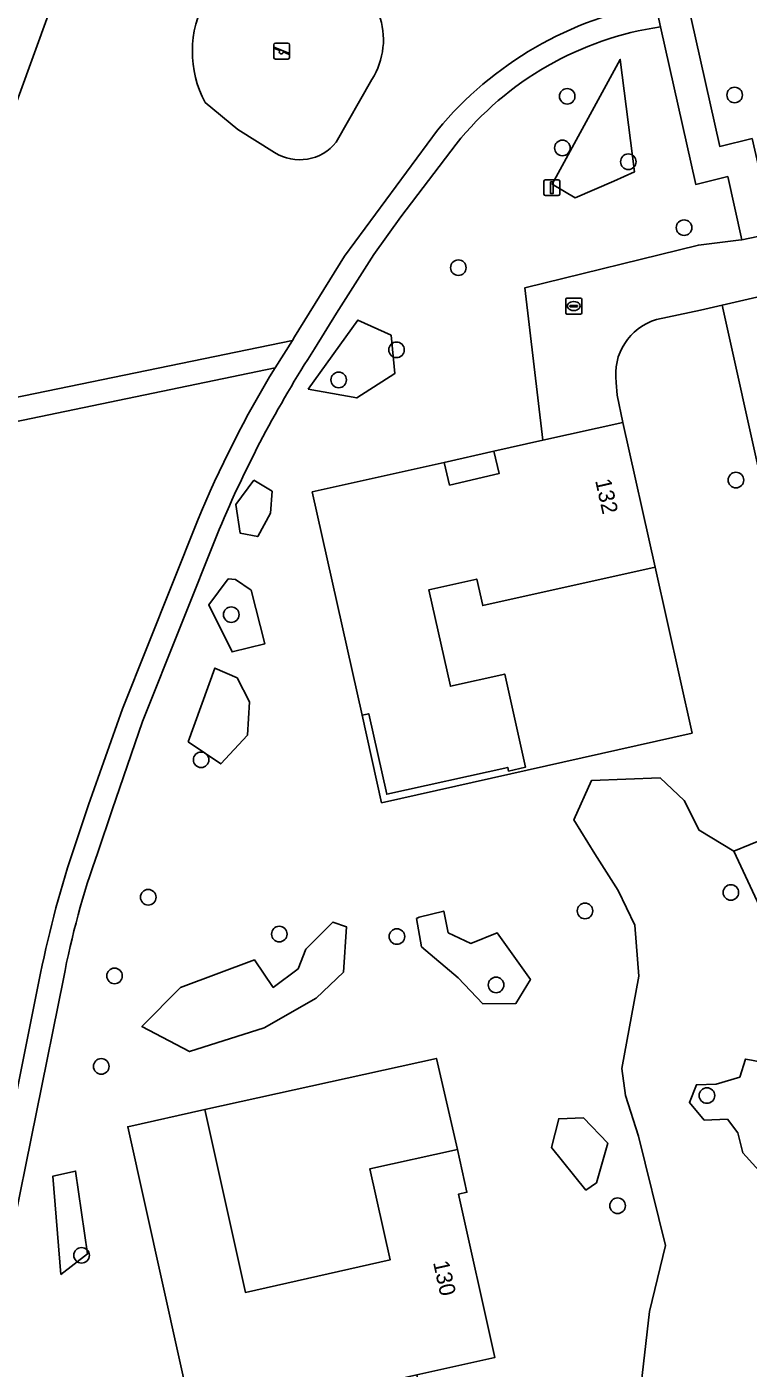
# Model space of a CAD drawing. Extents: x 156661 to 157576, y 383570 to 384425.
# Drawn here: x 156734.9 to 156780.2, y 383941.5 to 384025.8 of the extents above; entities that cross this region are included whole.
import ezdxf

# ---------------------------------------------------------------- set-up
doc = ezdxf.new("R2010")
doc.units = 0
for name, color, linetype in [('IMGEO_Boom', 7, 'Continuous'), ('IMGEO_Erf', 7, 'Continuous'), ('IMGEO_Groenvoorziening', 7, 'Continuous'), ('IMGEO_Lichtmast', 7, 'Continuous'), ('IMGEO_Meer_plas_ven_vijver', 7, 'Continuous'), ('IMGEO_Pand', 7, 'Continuous'), ('IMGEO_Pand_nummerreeks', 7, 'Continuous'), ('IMGEO_Pand_overbouw', 7, 'Continuous'), ('IMGEO_Rijbaan_lokaal_gesloten', 7, 'Continuous'), ('IMGEO_Rioolput', 7, 'Continuous'), ('IMGEO_Speelvoorziening', 7, 'Continuous'), ('IMGEO_Terreindeel_zand', 7, 'Continuous'), ('IMGEO_Voetpad_open', 7, 'Continuous')]:
    doc.layers.add(name, color=color, linetype=linetype)

msp = doc.modelspace()

# ---------------------------------------------------------------- linework, layer by layer
at = {"layer": 'IMGEO_Boom'}
for centre in [(156768.857, 384021.405), (156779.379, 384021.487), (156768.554, 384018.162), (156772.697, 384017.295), (156776.2, 384013.155), (156762.017, 384010.641), (156758.132, 384005.481), (156754.496, 384003.593), (156779.459, 383997.299), (156747.744, 383988.848), (156745.852, 383979.731), (156742.527, 383971.098), (156779.142, 383971.397), (156769.975, 383970.241), (156750.764, 383968.783), (156758.154, 383968.63), (156740.409, 383966.158), (156764.388, 383965.59), (156739.577, 383960.472), (156777.637, 383958.643), (156772.022, 383951.722), (156738.338, 383948.608)]:
    msp.add_circle(centre, 0.489, dxfattribs=at)
at = {"layer": 'IMGEO_Erf'}
for points in [[(156774.388, 383991.829), (156763.546, 383989.416), (156763.174, 383991.078), (156760.155, 383990.399), (156761.515, 383984.347), (156764.93, 383985.114), (156766.244, 383979.27), (156765.172, 383979.023), (156765.119, 383979.252), (156757.512, 383977.566), (156756.39, 383982.627), (156755.968, 383982.533), (156757.197, 383977.029), (156776.706, 383981.404)], [(156756.462, 383954.041), (156761.956, 383955.261), (156760.64, 383960.974), (156746.086, 383957.762), (156748.639, 383946.279), (156757.728, 383948.318)]]:
    msp.add_lwpolyline(points, close=True, dxfattribs=at)
at = {"layer": 'IMGEO_Groenvoorziening'}
for points in [[(156783.368, 384036.038), (156781.019, 384037.168), (156777.266, 384038.543), (156775.643, 384044.434), (156772.725, 384043.785), (156778.442, 384018.254), (156780.475, 384018.747), (156781.838, 384012.804), (156781.864, 384012.809), (156782.553, 384012.974), (156781.573, 384017.661), (156783.89, 384018.153), (156783.818, 384018.482), (156781.479, 384029.084)], [(156740.015, 384036.902), (156726.961, 384000.99), (156751.586, 384006.062), (156751.725, 384006.297), (156754.865, 384011.374), (156760.705, 384019.284)], [(156771.942, 384003.438), (156771.991, 384002.639), (156772.355, 384000.925), (156774.388, 383991.829), (156776.706, 383981.404), (156757.197, 383977.029), (156755.968, 383982.533), (156752.836, 383996.555), (156761.128, 383998.412), (156761.466, 383996.981), (156764.584, 383997.716), (156764.255, 383999.112), (156767.319, 383999.798), (156766.184, 384009.37), (156777.107, 384012.058), (156779.792, 384012.393), (156779.821, 384012.399), (156778.942, 384016.363), (156776.934, 384015.874), (156774.72, 384025.769)], [(156756.584, 384022.458), (156754.334, 384018.53)], [(156748.162, 384019.314), (156746.111, 384021.006)], [(156750.472, 384017.873), (156748.162, 384019.314)], [(156761.879, 384018.406), (156758.392, 384013.827), (156756.703, 384011.476), (156754.364, 384007.783), (156752.982, 384005.552)], [(156762.934, 383934.118), (156793.6, 383940.758), (156778.599, 384008.292)], [(156778.599, 384008.292), (156777.229, 384007.978), (156774.468, 384007.384)], [(156750.5, 384004.357), (156726.363, 383999.343), (156718.784, 383978.494), (156695.763, 383915.089), (156727.382, 383922.744), (156730.538, 383940.037), (156732.341, 383949.386), (156735.763, 383966.324)], [(156737.952, 383974.452), (156738.777, 383976.903), (156740.904, 383982.935), (156745.62, 383994.734)], [(156746.986, 383994.199), (156742.177, 383982.137), (156740.263, 383976.579), (156739.354, 383973.907)], [(156773.42, 383939.788), (156774.037, 383945.068), (156775.033, 383949.232), (156773.33, 383956.082), (156772.527, 383958.648), (156772.286, 383960.331), (156773.363, 383966.149), (156773.11, 383969.336), (156772.059, 383971.514), (156770.584, 383973.827), (156769.264, 383975.956), (156770.374, 383978.421), (156774.697, 383978.591), (156776.217, 383977.176), (156777.149, 383975.302), (156779.327, 383973.994), (156781.389, 383974.828)], [(156737.201, 383965.983), (156733.811, 383949.232), (156731.99, 383939.651), (156729.033, 383923.186), (156746.567, 383927.406), (156746.695, 383927.753)], [(156751.719, 383933.758), (156750.78, 383938.387), (156745.551, 383937.219), (156741.236, 383956.679), (156746.086, 383957.762), (156760.64, 383960.974), (156761.956, 383955.261), (156762.554, 383952.572), (156762.026, 383952.455), (156764.312, 383942.195), (156759.416, 383941.099), (156760.97, 383934.592)]]:
    msp.add_lwpolyline(points, dxfattribs=at)
for points in [[(156771.788, 384016.068), (156773.09, 384016.668), (156772.193, 384023.718), (156767.921, 384015.884), (156769.366, 384015.037)], [(156771.788, 384016.068), (156769.366, 384015.037), (156767.921, 384015.884), (156772.193, 384023.718), (156773.09, 384016.668)], [(156752.568, 384003.018), (156755.629, 384002.458), (156758.024, 384003.987), (156757.789, 384006.398), (156755.692, 384007.353)], [(156752.568, 384003.018), (156755.692, 384007.353), (156757.789, 384006.398), (156758.024, 384003.987), (156755.629, 384002.458)], [(156749.157, 383997.29), (156748.03, 383995.759), (156748.298, 383993.973), (156749.408, 383993.751), (156750.22, 383995.221), (156750.324, 383996.595)], [(156749.157, 383997.29), (156750.324, 383996.595), (156750.22, 383995.221), (156749.408, 383993.751), (156748.298, 383993.973), (156748.03, 383995.759)], [(156747.554, 383991.103), (156746.327, 383989.459), (156747.802, 383986.505), (156749.849, 383987.011), (156749, 383990.384), (156748.013, 383991.053)], [(156747.554, 383991.103), (156748.013, 383991.053), (156749, 383990.384), (156749.849, 383987.011), (156747.802, 383986.505), (156746.327, 383989.459)], [(156745.041, 383980.865), (156747.086, 383979.467), (156748.768, 383981.288), (156748.897, 383983.37), (156748.11, 383984.885), (156746.721, 383985.493)], [(156745.041, 383980.865), (156746.721, 383985.493), (156748.11, 383984.885), (156748.897, 383983.37), (156748.768, 383981.288), (156747.086, 383979.467)], [(156779.327, 383973.994), (156781.225, 383969.906), (156781.724, 383970.931), (156781.389, 383974.828)], [(156759.387, 383969.769), (156759.55, 383969.856), (156761.095, 383970.228), (156761.384, 383968.868), (156762.81, 383968.198), (156764.465, 383968.858), (156766.549, 383965.922), (156765.639, 383964.428), (156763.548, 383964.403), (156762.006, 383966.029), (156759.702, 383967.991)], [(156759.387, 383969.769), (156759.702, 383967.991), (156762.006, 383966.029), (156763.548, 383964.403), (156765.639, 383964.428), (156766.549, 383965.922), (156764.465, 383968.858), (156762.81, 383968.198), (156761.384, 383968.868), (156761.095, 383970.228), (156759.55, 383969.856)], [(156754.803, 383966.384), (156754.98, 383969.249), (156754.125, 383969.538), (156752.424, 383967.847), (156751.94, 383966.605), (156750.387, 383965.431), (156749.203, 383967.157), (156744.545, 383965.437), (156742.132, 383962.978), (156745.121, 383961.406), (156749.81, 383962.889), (156753.086, 383964.767)], [(156754.803, 383966.384), (156753.086, 383964.767), (156749.81, 383962.889), (156745.121, 383961.406), (156742.132, 383962.978), (156744.545, 383965.437), (156749.203, 383967.157), (156750.387, 383965.431), (156751.94, 383966.605), (156752.424, 383967.847), (156754.125, 383969.538), (156754.98, 383969.249)], [(156780.441, 383960.855), (156780.053, 383960.933), (156779.701, 383959.798), (156778.222, 383959.363), (156776.978, 383959.318), (156776.54, 383958.214), (156777.466, 383957.092), (156778.922, 383957.158), (156779.589, 383956.296), (156779.895, 383955.046), (156781.326, 383953.479), (156782.724, 383952.271), (156782.102, 383950.935), (156782.987, 383945.756), (156783.962, 383947.12), (156785.527, 383949.309), (156784.708, 383953.072), (156782.448, 383957.137), (156781.902, 383960.563)], [(156768.328, 383957.183), (156769.878, 383957.251), (156771.409, 383955.65), (156770.692, 383953.17), (156770.037, 383952.701), (156767.868, 383955.375)], [(156769.878, 383957.251), (156768.328, 383957.183), (156767.868, 383955.375), (156770.037, 383952.701), (156770.692, 383953.17), (156771.409, 383955.65)], [(156737.044, 383947.398), (156738.719, 383948.7), (156737.961, 383953.895), (156736.542, 383953.588)], [(156737.044, 383947.398), (156736.542, 383953.588), (156737.961, 383953.895), (156738.719, 383948.7)]]:
    msp.add_lwpolyline(points, close=True, dxfattribs=at)
for centre, radius, start, end in [((156752.604, 384024.966), 4.704, 327.78692, 72.04484), ((156752.094, 384024.225), 6.794, 151.08353, 208.28221), ((156778.326, 384004.644), 22.909, 99.87617, 140.28013), ((156777.663, 384005.757), 20.227, 98.36665, 141.29307), ((156752.04, 384020.338), 2.921, 237.54503, 321.76432), ((156775.479, 384003.955), 3.575, 106.42859, 188.32139), ((156814.276, 383965.92), 72.991, 147.11386, 157.20528), ((156810.796, 383967.731), 70.548, 148.72389, 157.49531), ((156801.471, 383952.987), 67.048, 161.32795, 168.52598), ((156788.672, 383956.253), 52.383, 160.30402, 169.29468)]:
    msp.add_arc(centre, radius, start, end, dxfattribs=at)
at = {"layer": 'IMGEO_Lichtmast'}
for p, q in [((156767.497, 384016.167), (156768.287, 384016.167)), ((156768.287, 384016.167), (156767.497, 384016.167)), ((156767.397, 384015.267), (156767.397, 384016.067)), ((156767.397, 384016.067), (156767.397, 384015.267)), ((156768.387, 384016.067), (156768.387, 384015.267)), ((156768.387, 384015.267), (156768.387, 384016.067)), ((156768.287, 384015.167), (156767.497, 384015.167)), ((156767.497, 384015.167), (156768.287, 384015.167))]:
    msp.add_line(p, q, dxfattribs=at)
msp.add_lwpolyline([(156767.817, 384016.042), (156767.967, 384016.042), (156767.967, 384015.292), (156767.817, 384015.292), (156767.817, 384016.042)], dxfattribs=at)
for centre, start, end in [((156767.497, 384016.067), 90, 180), ((156767.497, 384016.067), 90, 180), ((156768.287, 384016.067), 0, 90), ((156768.287, 384016.067), 360, 90), ((156767.497, 384015.267), 180, 270), ((156767.497, 384015.267), 180, 270), ((156768.287, 384015.267), 270, 0), ((156768.287, 384015.267), 270, 0)]:
    msp.add_arc(centre, 0.1, start, end, dxfattribs=at)
at = {"layer": 'IMGEO_Meer_plas_ven_vijver'}
for points in [[(156781.225, 383969.906), (156779.327, 383973.994), (156777.149, 383975.302), (156776.217, 383977.176), (156774.697, 383978.591), (156770.374, 383978.421), (156769.264, 383975.956), (156770.584, 383973.827), (156772.059, 383971.514), (156773.11, 383969.336), (156773.363, 383966.149), (156772.286, 383960.331), (156772.527, 383958.648), (156773.33, 383956.082), (156775.033, 383949.232), (156774.037, 383945.068), (156773.42, 383939.788)], [(156781.326, 383953.479), (156779.895, 383955.046), (156779.589, 383956.296), (156778.922, 383957.158), (156777.466, 383957.092), (156776.54, 383958.214), (156776.978, 383959.318), (156778.222, 383959.363), (156779.701, 383959.798), (156780.053, 383960.933), (156780.441, 383960.855)]]:
    msp.add_lwpolyline(points, dxfattribs=at)
at = {"layer": 'IMGEO_Pand'}
for points in [[(156772.355, 384000.925), (156767.319, 383999.798), (156764.255, 383999.112), (156764.584, 383997.716), (156761.466, 383996.981), (156761.128, 383998.412), (156752.836, 383996.555), (156755.968, 383982.533), (156756.39, 383982.627), (156757.512, 383977.566), (156765.119, 383979.252), (156765.172, 383979.023), (156766.244, 383979.27), (156764.93, 383985.114), (156761.515, 383984.347), (156760.155, 383990.399), (156763.174, 383991.078), (156763.546, 383989.416), (156774.388, 383991.829)], [(156762.026, 383952.455), (156762.554, 383952.572), (156761.956, 383955.261), (156756.462, 383954.041), (156757.728, 383948.318), (156748.639, 383946.279), (156746.086, 383957.762), (156741.236, 383956.679), (156745.551, 383937.219), (156750.78, 383938.387), (156756.644, 383939.698), (156758.081, 383940.019), (156757.925, 383940.765), (156759.416, 383941.099), (156764.312, 383942.195)]]:
    msp.add_lwpolyline(points, close=True, dxfattribs=at)
at = {"layer": 'IMGEO_Pand_overbouw'}
msp.add_lwpolyline([(156764.255, 383999.112), (156761.128, 383998.412), (156761.466, 383996.981), (156764.584, 383997.716)], close=True, dxfattribs=at)
at = {"layer": 'IMGEO_Rijbaan_lokaal_gesloten'}
for points in [[(156778.599, 384008.292), (156782.408, 384009.165), (156782.661, 384009.212), (156785.743, 384009.788), (156785.155, 384012.442), (156784.912, 384013.537), (156782.553, 384012.974), (156781.864, 384012.809), (156781.838, 384012.804), (156779.821, 384012.399), (156779.792, 384012.393), (156777.107, 384012.058), (156766.184, 384009.37), (156767.319, 383999.798), (156772.355, 384000.925), (156771.991, 384002.639), (156771.942, 384003.438)], [(156774.468, 384007.384), (156777.229, 384007.978), (156778.599, 384008.292)]]:
    msp.add_lwpolyline(points, dxfattribs=at)
msp.add_arc((156775.479, 384003.955), 3.575, 106.42859, 188.32139, dxfattribs=at)
at = {"layer": 'IMGEO_Rioolput'}
for p, q in [((156768.769, 384007.803), (156768.769, 384008.655)), ((156768.844, 384008.729), (156769.696, 384008.729)), ((156769.77, 384008.655), (156769.77, 384007.803)), ((156769.696, 384007.729), (156768.844, 384007.729)), ((156769.028, 384008.223), (156769.028, 384008.235)), ((156769.466, 384008.186), (156769.068, 384008.186)), ((156769.071, 384008.272), (156769.469, 384008.272)), ((156769.28, 384007.949), (156769.255, 384007.949)), ((156769.257, 384008.509), (156769.282, 384008.509)), ((156769.512, 384008.235), (156769.512, 384008.223))]:
    msp.add_line(p, q, dxfattribs=at)
for points in [[(156768.769, 384007.803), (156768.769, 384008.655)], [(156768.844, 384008.729), (156769.696, 384008.729)], [(156769.77, 384008.655), (156769.77, 384007.803)], [(156769.696, 384007.729), (156768.844, 384007.729)]]:
    msp.add_lwpolyline(points, dxfattribs=at)
for centre, radius, start, end in [((156768.846, 384008.653), 0.0765, 91.55205, 178.44795), ((156768.846, 384008.653), 0.0765, 91.55205, 178.44795), ((156769.694, 384008.653), 0.0765, 1.55205, 88.44795), ((156769.694, 384008.653), 0.0765, 1.55205, 88.44795), ((156768.846, 384007.805), 0.0765, 181.55205, 268.44795), ((156768.846, 384007.805), 0.0765, 181.55205, 268.44795), ((156769.068, 384008.232), 0.0403, 85.87752, 175.75265), ((156769.065, 384008.222), 0.0366, 178.93798, 274.71019), ((156769.469, 384008.229), 0.043, 264.86636, 352.45326), ((156769.473, 384008.234), 0.0386, 1.73085, 96.63898), ((156769.694, 384007.805), 0.0765, 271.55205, 358.44795), ((156769.694, 384007.805), 0.0765, 271.55205, 358.44795)]:
    msp.add_arc(centre, radius, start, end, dxfattribs=at)
for centre, major_axis, ratio, start_param, end_param in [((156769.256, 384008.229), (-0.387, 0.002), 0.722429, 4.712389, 7.853982), ((156769.281, 384008.229), (-0.39, 0.002), 0.717154, 1.570796, 4.712389)]:
    msp.add_ellipse(centre, major_axis=major_axis, ratio=ratio, start_param=start_param, end_param=end_param, dxfattribs=at)
at = {"layer": 'IMGEO_Speelvoorziening'}
for p, q in [((156750.418, 384023.848), (156750.418, 384024.648)), ((156750.418, 384024.648), (156750.418, 384023.848)), ((156750.518, 384024.748), (156751.308, 384024.748)), ((156751.308, 384024.748), (156750.518, 384024.748)), ((156751.408, 384024.648), (156751.408, 384023.848)), ((156751.408, 384023.848), (156751.408, 384024.648)), ((156750.801, 384024.276), (156750.462, 384024.413)), ((156750.487, 384024.473), (156751.363, 384024.12)), ((156751.308, 384023.748), (156750.518, 384023.748)), ((156750.518, 384023.748), (156751.308, 384023.748)), ((156751.339, 384024.06), (156750.999, 384024.197))]:
    msp.add_line(p, q, dxfattribs=at)
for centre, radius, start, end in [((156750.518, 384024.648), 0.1, 90, 180), ((156750.518, 384024.648), 0.1, 90, 180), ((156751.308, 384024.648), 0.1, 0, 90), ((156751.308, 384024.648), 0.1, 360, 90), ((156750.518, 384023.848), 0.1, 180, 270), ((156750.518, 384023.848), 0.1, 180, 270), ((156750.475, 384024.443), 0.0327, 68.07798, 248.07798), ((156750.88, 384024.186), 0.12, 130.99278, 5.16318), ((156751.308, 384023.848), 0.1, 270, 0), ((156751.308, 384023.848), 0.1, 270, 0), ((156751.351, 384024.09), 0.0327, 248.07798, 68.07798)]:
    msp.add_arc(centre, radius, start, end, dxfattribs=at)
at = {"layer": 'IMGEO_Terreindeel_zand'}
for points in [[(156754.334, 384018.53), (156756.584, 384022.458)], [(156746.111, 384021.006), (156748.162, 384019.314), (156750.472, 384017.873)]]:
    msp.add_lwpolyline(points, dxfattribs=at)
for centre, radius, start, end in [((156752.604, 384024.966), 4.704, 327.78692, 72.04484), ((156752.094, 384024.225), 6.794, 151.08353, 208.28221), ((156752.04, 384020.338), 2.921, 237.54503, 321.76432)]:
    msp.add_arc(centre, radius, start, end, dxfattribs=at)
at = {"layer": 'IMGEO_Voetpad_open'}
for points in [[(156772.725, 384043.785), (156770.782, 384043.37), (156774.397, 384027.214), (156774.72, 384025.769), (156776.934, 384015.874), (156778.942, 384016.363), (156779.821, 384012.399), (156781.838, 384012.804), (156780.475, 384018.747), (156778.442, 384018.254)], [(156781.235, 384006.002), (156783.294, 384006.453), (156782.661, 384009.212), (156782.408, 384009.165), (156778.599, 384008.292), (156793.6, 383940.758), (156795.59, 383941.189), (156786.905, 383980.313), (156788.201, 383980.63), (156789.615, 383980.975), (156789.272, 383982.501), (156787.859, 383982.142), (156786.625, 383981.827)], [(156750.5, 384004.357), (156751.586, 384006.062), (156726.961, 384000.99), (156726.363, 383999.343)]]:
    msp.add_lwpolyline(points, close=True, dxfattribs=at)
for points in [[(156737.507, 384036.302), (156716.373, 383978.18), (156709.217, 383958.49), (156701.659, 383937.694), (156690.408, 383906.735), (156677.045, 383870.138), (156675.34, 383865.46), (156676.825, 383863.032), (156678.542, 383867.746), (156678.565, 383867.81), (156682.477, 383878.585), (156685.05, 383885.669), (156685.231, 383886.168), (156686.812, 383890.508), (156687.008, 383891.046), (156692.453, 383905.972), (156693.23, 383908.111), (156693.984, 383910.189), (156695.166, 383913.444), (156695.763, 383915.089), (156718.784, 383978.494), (156726.363, 383999.343), (156726.961, 384000.99), (156740.015, 384036.902)], [(156760.705, 384019.284), (156754.865, 384011.374), (156751.725, 384006.297), (156751.586, 384006.062), (156750.5, 384004.357)], [(156752.982, 384005.552), (156754.364, 384007.783), (156756.703, 384011.476), (156758.392, 384013.827), (156761.879, 384018.406)], [(156745.62, 383994.734), (156740.904, 383982.935), (156738.777, 383976.903), (156737.952, 383974.452)], [(156739.354, 383973.907), (156740.263, 383976.579), (156742.177, 383982.137), (156746.986, 383994.199)], [(156735.763, 383966.324), (156732.341, 383949.386), (156730.538, 383940.037), (156727.382, 383922.744), (156695.763, 383915.089), (156695.166, 383913.444), (156727.186, 383921.164), (156728.818, 383921.585), (156745.94, 383925.711), (156746.567, 383927.406), (156729.033, 383923.186), (156731.99, 383939.651), (156733.811, 383949.232), (156737.201, 383965.983)]]:
    msp.add_lwpolyline(points, dxfattribs=at)
for centre, radius, start, end in [((156778.326, 384004.644), 22.909, 99.87617, 140.28013), ((156777.663, 384005.757), 20.227, 98.36665, 141.29307), ((156814.276, 383965.92), 72.991, 147.11386, 157.20528), ((156810.796, 383967.731), 70.548, 148.72389, 157.49531), ((156801.471, 383952.987), 67.048, 161.32795, 168.52598), ((156788.672, 383956.253), 52.383, 160.30402, 169.29468)]:
    msp.add_arc(centre, radius, start, end, dxfattribs=at)

# ---------------------------------------------------------------- texts
at = {"layer": 'IMGEO_Pand_nummerreeks'}
for s, rotation, p in [('132', 282.59913, (156770.609, 383997.272)), ('130', 282.55902, (156760.421, 383948.161))]:
    msp.add_text(s, height=1, rotation=rotation, dxfattribs=at).set_placement(p)

doc.saveas('drawing.dxf')
